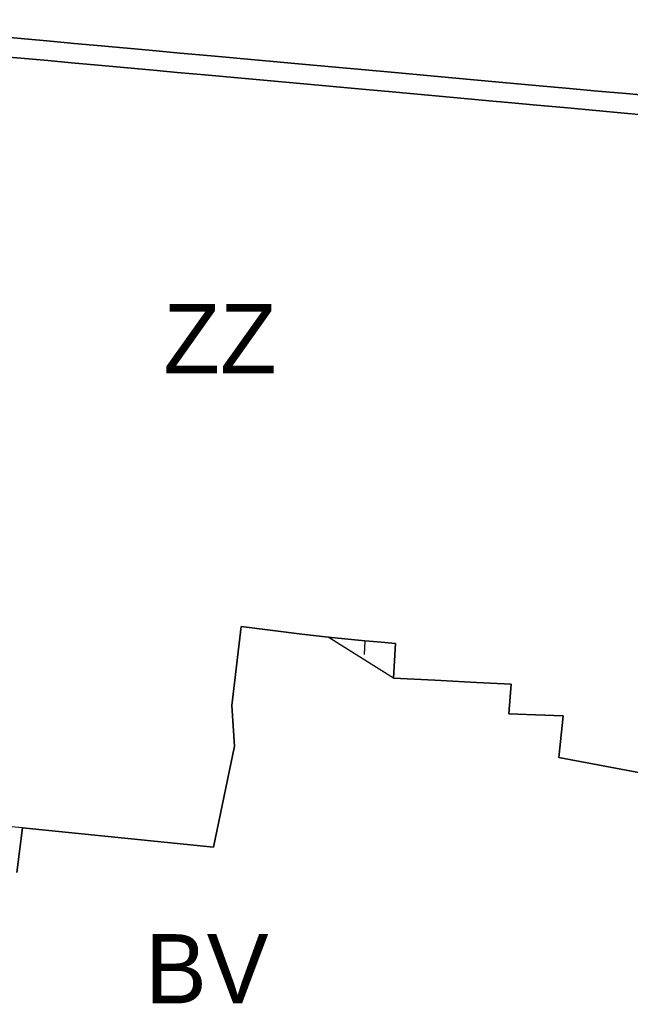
# Model space of a CAD drawing. Extents: x -555509 to -553005, y -1186756 to -1182560.
# Drawn here: x -554326.9 to -554203.4, y -1184302.8 to -1184103.8 of the extents above; entities that cross this region are included whole.
import ezdxf

# ---------------------------------------------------------------- set-up
doc = ezdxf.new("R2010")
doc.units = 0
for name, color, linetype in [('Level 26', 7, 'Continuous'), ('Level 36', 7, 'Continuous'), ('Level 52', 7, 'Continuous'), ('Level 59', 7, 'Continuous'), ('Level 6', 7, 'Continuous'), ('OBRYS_PLOCH', 7, 'Continuous'), ('stav_AP', 7, 'Continuous'), ('stav_BV', 7, 'Continuous'), ('stav_ZZ', 7, 'Continuous')]:
    doc.layers.add(name, color=color, linetype=linetype)

msp = doc.modelspace()

# ---------------------------------------------------------------- linework, layer by layer
at = {"layer": 'Level 26'}
for p, q in [((-554331.76, -1184111.1), (-554321.21, -1184112.07)), ((-554321.21, -1184112.07), (-554316.4, -1184112.5)), ((-554316.4, -1184112.5), (-554311.04, -1184112.99)), ((-554299.16, -1184114.07), (-554295.01, -1184114.45)), ((-554227.34, -1184120.61), (-554223.05, -1184121)), ((-554223.05, -1184121), (-554216.11, -1184121.64))]:
    msp.add_line(p, q, dxfattribs=at)
for points in [[(-554165.91, -1184122.25), (-554184.57, -1184120.55), (-554194.22, -1184119.67), (-554204.27, -1184118.75), (-554209.96, -1184118.23), (-554215.7, -1184117.71), (-554222.5, -1184117.09), (-554230.67, -1184116.35), (-554238.72, -1184115.61), (-554251.02, -1184114.49), (-554269.76, -1184112.78), (-554288.18, -1184111.1), (-554294.43, -1184110.53), (-554300.68, -1184109.96), (-554310.42, -1184109.07), (-554315.86, -1184108.58), (-554320.66, -1184108.14), (-554331.2, -1184107.18), (-554338.84, -1184106.48), (-554346.65, -1184105.77), (-554351.87, -1184105.29), (-554357.35, -1184104.79), (-554368.51, -1184103.78)], [(-554311.04, -1184112.99), (-554301.35, -1184113.88), (-554299.16, -1184114.07)], [(-554295.01, -1184114.45), (-554288.67, -1184115.03), (-554270.18, -1184116.71), (-554256.91, -1184117.92), (-554251.53, -1184118.41), (-554239.17, -1184119.54)], [(-554239.17, -1184119.54), (-554231.18, -1184120.26), (-554227.34, -1184120.61)], [(-554216.11, -1184121.64), (-554210.36, -1184122.16), (-554204.66, -1184122.68), (-554194.61, -1184123.59)]]:
    msp.add_lwpolyline(points, dxfattribs=at)
at = {"layer": 'Level 36'}
for points in [[(-554169.73, -1184199.7), (-554170.35, -1184212.11), (-554174.39, -1184232.45), (-554179.9, -1184260.17), (-554198.2, -1184256.75), (-554207.51, -1184255), (-554217.86, -1184253.07), (-554216.99, -1184244.62), (-554222.6, -1184244.41), (-554228, -1184244.2), (-554227.5, -1184238.22), (-554234.54, -1184237.86), (-554242.91, -1184237.42), (-554251.27, -1184236.99)], [(-554283.1, -1184235.02), (-554284, -1184242.55), (-554283.44, -1184250.8), (-554287.72, -1184271.23), (-554326.33, -1184267.32), (-554332.24, -1184266.72), (-554358.07, -1184264.1), (-554362.22, -1184263.55), (-554366.82, -1184262.94), (-554372.66, -1184262.44), (-554378.6, -1184261.72), (-554381.18, -1184261.48), (-554389.53, -1184260.75), (-554408.36, -1184258.58), (-554410.7, -1184258.35), (-554415.69, -1184257.85), (-554417.69, -1184257.65), (-554425.5, -1184256.87), (-554423.54, -1184240.08), (-554428.47, -1184239.51), (-554430.45, -1184239.27), (-554435.88, -1184238.64), (-554434.03, -1184222.84)], [(-554251.27, -1184236.99), (-554264.48, -1184228.74), (-554269.85, -1184228.08), (-554282.09, -1184226.58), (-554283.1, -1184235.02)]]:
    msp.add_lwpolyline(points, dxfattribs=at)
at = {"layer": 'Level 52'}
for p, q in [((-554257.07, -1184229.43), (-554264.48, -1184228.74)), ((-554250.87, -1184230.01), (-554254.53, -1184229.67)), ((-554250.87, -1184230.01), (-554251.27, -1184236.99))]:
    msp.add_line(p, q, dxfattribs=at)
for points in [[(-554139.8, -1184133.76), (-554150.81, -1184130.59), (-554166.1, -1184126.19), (-554168.02, -1184165.33), (-554169.59, -1184196.9), (-554170.35, -1184212.11), (-554174.39, -1184232.45), (-554179.9, -1184260.17), (-554198.2, -1184256.75), (-554207.51, -1184255), (-554217.86, -1184253.07), (-554216.99, -1184244.62), (-554222.6, -1184244.41), (-554228, -1184244.2), (-554227.5, -1184238.22), (-554234.54, -1184237.86), (-554242.91, -1184237.42), (-554251.27, -1184236.99)], [(-554264.48, -1184228.74), (-554269.85, -1184228.08), (-554282.09, -1184226.58), (-554284, -1184242.55), (-554283.44, -1184250.8), (-554287.72, -1184271.23), (-554326.33, -1184267.32), (-554327.43, -1184276.33)], [(-554254.53, -1184229.67), (-554257.07, -1184229.43), (-554257.22, -1184232.19)]]:
    msp.add_lwpolyline(points, dxfattribs=at)
at = {"layer": 'Level 6'}
for p, q in [((-554257.07, -1184229.43), (-554264.48, -1184228.74)), ((-554254.53, -1184229.67), (-554257.07, -1184229.43)), ((-554250.87, -1184230.01), (-554254.53, -1184229.67)), ((-554251.27, -1184236.99), (-554250.87, -1184230.01))]:
    msp.add_line(p, q, dxfattribs=at)
for points in [[(-554139.99, -1184133.71), (-554150.81, -1184130.59), (-554166.1, -1184126.19), (-554168.02, -1184165.33), (-554169.59, -1184196.9), (-554170.35, -1184212.11), (-554174.39, -1184232.45), (-554179.9, -1184260.17), (-554198.2, -1184256.75), (-554207.51, -1184255), (-554217.86, -1184253.07), (-554216.99, -1184244.62), (-554222.6, -1184244.41), (-554228, -1184244.2), (-554227.5, -1184238.22), (-554234.54, -1184237.86), (-554242.91, -1184237.42), (-554251.27, -1184236.99)], [(-554264.48, -1184228.74), (-554269.85, -1184228.08), (-554282.09, -1184226.58), (-554284, -1184242.55), (-554283.44, -1184250.8), (-554287.72, -1184271.23), (-554326.33, -1184267.32), (-554327.43, -1184276.33)]]:
    msp.add_lwpolyline(points, dxfattribs=at)
at = {"layer": 'OBRYS_PLOCH'}
for p, q in [((-554331.76, -1184111.1), (-554321.21, -1184112.07)), ((-554321.21, -1184112.07), (-554331.76, -1184111.1)), ((-554321.21, -1184112.07), (-554316.4, -1184112.5)), ((-554316.4, -1184112.5), (-554321.21, -1184112.07)), ((-554316.4, -1184112.5), (-554311.04, -1184112.99)), ((-554311.04, -1184112.99), (-554316.4, -1184112.5)), ((-554301.35, -1184113.88), (-554311.04, -1184112.99)), ((-554299.16, -1184114.07), (-554301.35, -1184113.88)), ((-554299.16, -1184114.07), (-554295.01, -1184114.45)), ((-554295.01, -1184114.45), (-554299.16, -1184114.07)), ((-554288.67, -1184115.03), (-554295.01, -1184114.45)), ((-554270.18, -1184116.71), (-554288.67, -1184115.03)), ((-554256.91, -1184117.92), (-554270.18, -1184116.71)), ((-554251.53, -1184118.41), (-554256.91, -1184117.92)), ((-554239.17, -1184119.54), (-554251.53, -1184118.41)), ((-554227.34, -1184120.61), (-554223.05, -1184121)), ((-554223.05, -1184121), (-554227.34, -1184120.61)), ((-554223.05, -1184121), (-554216.11, -1184121.64)), ((-554216.11, -1184121.64), (-554223.05, -1184121)), ((-554210.36, -1184122.16), (-554216.11, -1184121.64)), ((-554204.66, -1184122.68), (-554210.36, -1184122.16)), ((-554194.61, -1184123.59), (-554204.66, -1184122.68)), ((-554284, -1184242.55), (-554282.09, -1184226.58)), ((-554282.09, -1184226.58), (-554269.85, -1184228.08)), ((-554264.48, -1184228.74), (-554269.85, -1184228.08)), ((-554269.85, -1184228.08), (-554264.48, -1184228.74)), ((-554257.07, -1184229.43), (-554264.48, -1184228.74)), ((-554264.48, -1184228.74), (-554257.07, -1184229.43)), ((-554254.53, -1184229.67), (-554257.07, -1184229.43)), ((-554257.07, -1184229.43), (-554254.53, -1184229.67)), ((-554250.87, -1184230.01), (-554254.53, -1184229.67)), ((-554254.53, -1184229.67), (-554250.87, -1184230.01)), ((-554251.27, -1184236.99), (-554250.87, -1184230.01)), ((-554250.87, -1184230.01), (-554251.27, -1184236.99)), ((-554242.91, -1184237.42), (-554251.27, -1184236.99)), ((-554251.27, -1184236.99), (-554242.91, -1184237.42)), ((-554234.54, -1184237.86), (-554242.91, -1184237.42)), ((-554242.91, -1184237.42), (-554234.54, -1184237.86)), ((-554227.5, -1184238.22), (-554234.54, -1184237.86)), ((-554234.54, -1184237.86), (-554227.5, -1184238.22)), ((-554228, -1184244.2), (-554227.5, -1184238.22)), ((-554227.5, -1184238.22), (-554228, -1184244.2)), ((-554284, -1184242.55), (-554283.44, -1184250.8)), ((-554283.44, -1184250.8), (-554284, -1184242.55)), ((-554222.6, -1184244.41), (-554228, -1184244.2)), ((-554216.99, -1184244.62), (-554222.6, -1184244.41)), ((-554217.86, -1184253.07), (-554216.99, -1184244.62)), ((-554283.44, -1184250.8), (-554287.72, -1184271.23)), ((-554207.51, -1184255), (-554217.86, -1184253.07)), ((-554198.2, -1184256.75), (-554207.51, -1184255)), ((-554207.51, -1184255), (-554198.2, -1184256.75)), ((-554326.33, -1184267.32), (-554327.43, -1184276.33)), ((-554327.43, -1184276.33), (-554326.33, -1184267.32)), ((-554287.72, -1184271.23), (-554326.33, -1184267.32))]:
    msp.add_line(p, q, dxfattribs=at)
for points in [[(-554165.91, -1184122.25), (-554184.57, -1184120.55), (-554194.22, -1184119.67), (-554204.27, -1184118.75), (-554209.96, -1184118.23), (-554215.7, -1184117.71), (-554222.5, -1184117.09), (-554230.67, -1184116.35), (-554238.72, -1184115.61), (-554251.02, -1184114.49), (-554269.76, -1184112.78), (-554288.18, -1184111.1), (-554294.43, -1184110.53), (-554300.68, -1184109.96), (-554310.42, -1184109.07), (-554315.86, -1184108.58), (-554320.66, -1184108.14), (-554331.2, -1184107.18), (-554338.84, -1184106.48), (-554346.65, -1184105.77), (-554351.87, -1184105.29), (-554357.35, -1184104.79), (-554368.51, -1184103.78)], [(-554368.51, -1184103.78), (-554357.35, -1184104.79), (-554351.87, -1184105.29), (-554346.65, -1184105.77), (-554338.84, -1184106.48), (-554331.2, -1184107.18), (-554320.66, -1184108.14), (-554315.86, -1184108.58), (-554310.42, -1184109.07), (-554300.68, -1184109.96), (-554294.43, -1184110.53), (-554288.18, -1184111.1), (-554269.76, -1184112.78), (-554251.02, -1184114.49), (-554238.72, -1184115.61), (-554230.67, -1184116.35), (-554222.5, -1184117.09), (-554215.7, -1184117.71), (-554209.96, -1184118.23), (-554204.27, -1184118.75), (-554194.22, -1184119.67), (-554184.57, -1184120.55), (-554165.91, -1184122.25)], [(-554311.04, -1184112.99), (-554301.35, -1184113.88), (-554299.16, -1184114.07)], [(-554295.01, -1184114.45), (-554288.67, -1184115.03), (-554270.18, -1184116.71), (-554256.91, -1184117.92), (-554251.53, -1184118.41), (-554239.17, -1184119.54)], [(-554239.17, -1184119.54), (-554231.18, -1184120.26), (-554227.34, -1184120.61)], [(-554227.34, -1184120.61), (-554231.18, -1184120.26), (-554239.17, -1184119.54)], [(-554216.11, -1184121.64), (-554210.36, -1184122.16), (-554204.66, -1184122.68), (-554194.61, -1184123.59)], [(-554269.85, -1184228.08), (-554282.09, -1184226.58), (-554284, -1184242.55)], [(-554228, -1184244.2), (-554222.6, -1184244.41), (-554216.99, -1184244.62)], [(-554216.99, -1184244.62), (-554217.86, -1184253.07), (-554207.51, -1184255)], [(-554326.33, -1184267.32), (-554287.72, -1184271.23), (-554283.44, -1184250.8)]]:
    msp.add_lwpolyline(points, dxfattribs=at)
at = {"layer": 'stav_AP'}
msp.add_lwpolyline([(-554368.51, -1184103.78), (-554357.35, -1184104.79), (-554351.87, -1184105.29), (-554346.65, -1184105.77), (-554338.84, -1184106.48), (-554331.2, -1184107.18), (-554320.66, -1184108.14), (-554315.86, -1184108.58), (-554310.42, -1184109.07), (-554300.68, -1184109.96), (-554294.43, -1184110.53), (-554288.18, -1184111.1), (-554269.76, -1184112.78), (-554251.02, -1184114.49), (-554238.72, -1184115.61), (-554230.67, -1184116.35), (-554222.5, -1184117.09), (-554215.7, -1184117.71), (-554209.96, -1184118.23), (-554204.27, -1184118.75), (-554194.22, -1184119.67), (-554184.57, -1184120.55), (-554165.91, -1184122.25)], dxfattribs=at)
at = {"layer": 'stav_BV'}
for p, q in [((-554282.09, -1184226.58), (-554284, -1184242.55)), ((-554257.07, -1184229.43), (-554264.48, -1184228.74)), ((-554254.53, -1184229.67), (-554257.07, -1184229.43)), ((-554250.87, -1184230.01), (-554254.53, -1184229.67)), ((-554251.27, -1184236.99), (-554250.87, -1184230.01)), ((-554242.91, -1184237.42), (-554251.27, -1184236.99)), ((-554234.54, -1184237.86), (-554242.91, -1184237.42)), ((-554227.5, -1184238.22), (-554234.54, -1184237.86)), ((-554228, -1184244.2), (-554227.5, -1184238.22)), ((-554284, -1184242.55), (-554283.44, -1184250.8)), ((-554326.33, -1184267.32), (-554327.43, -1184276.33))]:
    msp.add_line(p, q, dxfattribs=at)
for points in [[(-554264.48, -1184228.74), (-554269.85, -1184228.08), (-554282.09, -1184226.58)], [(-554216.99, -1184244.62), (-554222.6, -1184244.41), (-554228, -1184244.2)], [(-554207.51, -1184255), (-554217.86, -1184253.07), (-554216.99, -1184244.62)], [(-554283.44, -1184250.8), (-554287.72, -1184271.23), (-554326.33, -1184267.32)], [(-554179.9, -1184260.17), (-554198.2, -1184256.75), (-554207.51, -1184255)]]:
    msp.add_lwpolyline(points, dxfattribs=at)
at = {"layer": 'stav_ZZ'}
for p, q in [((-554321.21, -1184112.07), (-554331.76, -1184111.1)), ((-554316.4, -1184112.5), (-554321.21, -1184112.07)), ((-554311.04, -1184112.99), (-554316.4, -1184112.5)), ((-554295.01, -1184114.45), (-554299.16, -1184114.07)), ((-554223.05, -1184121), (-554227.34, -1184120.61)), ((-554216.11, -1184121.64), (-554223.05, -1184121)), ((-554210.36, -1184122.16), (-554216.11, -1184121.64)), ((-554204.66, -1184122.68), (-554210.36, -1184122.16)), ((-554194.61, -1184123.59), (-554204.66, -1184122.68)), ((-554284, -1184242.55), (-554282.09, -1184226.58)), ((-554282.09, -1184226.58), (-554269.85, -1184228.08)), ((-554269.85, -1184228.08), (-554264.48, -1184228.74)), ((-554264.48, -1184228.74), (-554257.07, -1184229.43)), ((-554257.07, -1184229.43), (-554254.53, -1184229.67)), ((-554254.53, -1184229.67), (-554250.87, -1184230.01)), ((-554250.87, -1184230.01), (-554251.27, -1184236.99)), ((-554251.27, -1184236.99), (-554242.91, -1184237.42)), ((-554242.91, -1184237.42), (-554234.54, -1184237.86)), ((-554234.54, -1184237.86), (-554227.5, -1184238.22)), ((-554227.5, -1184238.22), (-554228, -1184244.2)), ((-554283.44, -1184250.8), (-554284, -1184242.55)), ((-554228, -1184244.2), (-554222.6, -1184244.41)), ((-554222.6, -1184244.41), (-554216.99, -1184244.62)), ((-554216.99, -1184244.62), (-554217.86, -1184253.07)), ((-554217.86, -1184253.07), (-554207.51, -1184255)), ((-554207.51, -1184255), (-554198.2, -1184256.75)), ((-554327.43, -1184276.33), (-554326.33, -1184267.32))]:
    msp.add_line(p, q, dxfattribs=at)
for points in [[(-554299.16, -1184114.07), (-554301.35, -1184113.88), (-554311.04, -1184112.99)], [(-554256.91, -1184117.92), (-554270.18, -1184116.71), (-554288.67, -1184115.03), (-554295.01, -1184114.45)], [(-554239.17, -1184119.54), (-554251.53, -1184118.41), (-554256.91, -1184117.92)], [(-554227.34, -1184120.61), (-554231.18, -1184120.26), (-554239.17, -1184119.54)], [(-554326.33, -1184267.32), (-554287.72, -1184271.23), (-554283.44, -1184250.8)]]:
    msp.add_lwpolyline(points, dxfattribs=at)

# ---------------------------------------------------------------- texts
at = {"layer": 'Level 59'}
for s, p in [('ZZ', (-554297.82, -1184175.33)), ('BV', (-554301.54, -1184302.8))]:
    msp.add_text(s, height=14, dxfattribs=at).set_placement(p)

doc.saveas('drawing.dxf')
